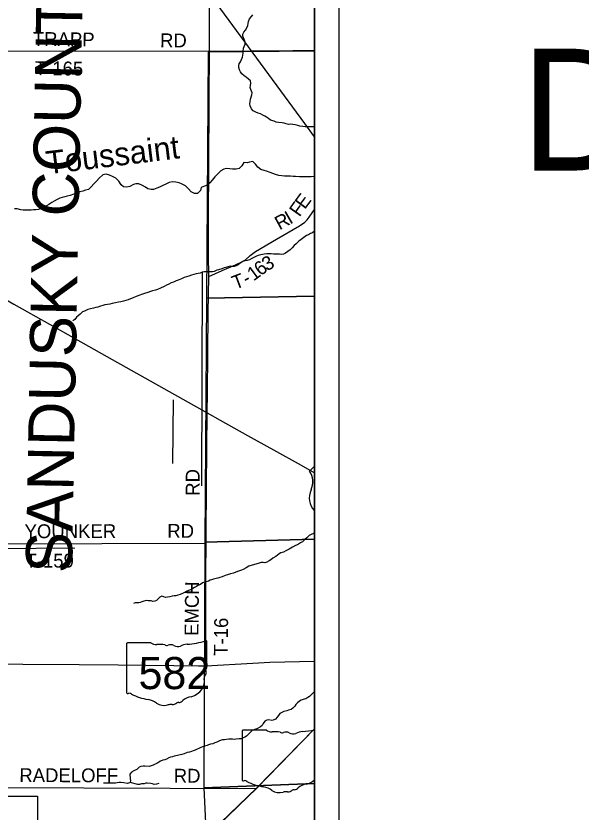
# Model space of a CAD drawing. Extents: x 0 to 34, y 0 to 22.
# Drawn here: x 7.676 to 9.993, y 16.867 to 20.135 of the extents above; entities that cross this region are included whole.
import ezdxf

# ---------------------------------------------------------------- set-up
doc = ezdxf.new("R2010")
doc.units = 0
for name, color, linetype in [('GM_X_City_Street', 7, 'Continuous'), ('GM_X_Corporation_Text', 7, 'Continuous'), ('GM_X_County_Text', 7, 'Continuous'), ('GM_X_Major_River', 7, 'Continuous'), ('GM_X_Major_River_Text', 7, 'Continuous'), ('GM_X_Minor_River', 7, 'Continuous'), ('GM_X_Rail_Line', 7, 'Continuous'), ('GM_X_State_Location', 7, 'Continuous'), ('GM_X_State_Route', 7, 'Continuous'), ('GM_X_State_Shield', 7, 'Continuous'), ('GM_X_Township_Road', 7, 'Continuous'), ('GM_X_Township_Road_Text', 7, 'Continuous'), ('GM_X_US_Route', 7, 'Continuous'), ('GM_X_US_Shield', 7, 'Continuous'), ('SH_Cut_Line', 7, 'Continuous'), ('SH_Data', 7, 'Continuous'), ('SH_Text', 7, 'Continuous')]:
    doc.layers.add(name, color=color, linetype=linetype)

msp = doc.modelspace()

# ---------------------------------------------------------------- linework, layer by layer
at = {"layer": 'GM_X_City_Street'}
for points in [[(8.9, 18.9838), (8.9, 19.99), (8.465, 19.986), (8.4572, 18.9756)], [(8.9, 17.9873), (8.9, 18.9838), (8.4572, 18.9756), (8.451, 17.9744)], [(8.9, 16.9842), (8.9, 17.9873), (8.451, 17.9744), (8.447, 16.9667)], [(8.9, 16.0164), (8.9, 16.9842), (8.447, 16.9667), (8.4914, 16.018), (8.4978, 16.0183)]]:
    msp.add_lwpolyline(points, close=True, dxfattribs=at)
at = {"layer": 'GM_X_Corporation_Text'}
for p, q in [((8.6032, 17.1993), (8.6032, 16.9992)), ((8.7029, 17.2028), (8.6063, 17.2028)), ((8.9, 16.9992), (8.9, 17.2043))]:
    msp.add_line(p, q, dxfattribs=at)
for centre, major_axis, start_param, end_param in [((8.6069, 17.1997), (0.00382, 0), 1.727492, 3.291633), ((8.7259, 17.226), (0.037, 0), 4.042888, 4.731792), ((8.7382, 17.0904), (0.133, 0), 1.404758, 1.657859), ((8.7684, 17.2008), (0.0107, 0), 3.836095, 5.185415), ((8.7841, 17.1776), (0.0222, 0), 0.950623, 2.079405), ((8.8127, 17.2094), (0.0267, 0), 4.08156, 5.145723), ((8.8599, 17.1416), (0.0703, 0), 1.699012, 2.107814), ((8.8153, 17.4756), (0.3495, 0), 4.814394, 4.957024), ((8.607, 16.9988), (0.00385, 0), 2.993084, 4.5083), ((8.6076, 17.0192), (0.0294, 0), 4.665946, 4.897461), ((8.6136, 16.9876), (0.0106, 0), 0.519207, 1.627899), ((8.7474, 17.1674), (0.2524, 0), 4.195997, 4.488961), ((8.8349, 17.0459), (0.0874, 0), 5.101753, 5.55198), ((8.6721, 16.9093), (0.079, 0), 0.823519, 1.323587), ((8.8111, 16.9798), (0.0282, 0), 4.937069, 5.64225), ((8.8718, 16.943), (0.0479, 0), 1.647645, 2.488434), ((8.7576, 16.9867), (0.0501, 0), 4.026481, 4.996735), ((8.7865, 16.9175), (0.0412, 0), 1.495662, 1.94098), ((8.7902, 16.9717), (0.0267, 0), 4.691044, 5.507374), ((8.8143, 16.9523), (0.00752, 0), 1.147584, 2.315152)]:
    msp.add_ellipse(centre, major_axis=major_axis, ratio=0.8, start_param=start_param, end_param=end_param, dxfattribs=at)
at = {"layer": 'GM_X_Major_River'}
for points in [[(8.9, 19.4752), (8.8872, 19.4736), (8.8747, 19.4741), (8.8644, 19.4738), (8.8504, 19.4735), (8.8394, 19.4744), (8.8227, 19.4757), (8.8125, 19.4761), (8.8019, 19.477), (8.7924, 19.477), (8.7769, 19.4775), (8.767, 19.4776), (8.7542, 19.4792), (8.7402, 19.4843), (8.7292, 19.4881), (8.7183, 19.4924), (8.7039, 19.4971), (8.6941, 19.5002), (8.6797, 19.5041), (8.6681, 19.5137), (8.6583, 19.5266), (8.6478, 19.537), (8.6345, 19.5348), (8.6243, 19.5322), (8.611, 19.5327), (8.6022, 19.5199), (8.5911, 19.5086), (8.5785, 19.5053), (8.5641, 19.5054), (8.5531, 19.507), (8.5399, 19.5078), (8.5285, 19.5056), (8.5163, 19.4982), (8.5037, 19.4865), (8.4922, 19.4741), (8.4803, 19.4609), (8.4715, 19.4492), (8.4608, 19.4402), (8.4494, 19.4357), (8.4353, 19.4305), (8.4325, 19.4176)], [(8.4325, 19.4176), (8.4207, 19.4059), (8.4085, 19.406), (8.3953, 19.4122), (8.3841, 19.4252), (8.3713, 19.4374), (8.3573, 19.4444), (8.3453, 19.4494), (8.3313, 19.4529), (8.3165, 19.4534), (8.3047, 19.4509), (8.288, 19.443), (8.2785, 19.4385), (8.2644, 19.4318), (8.2545, 19.4277), (8.2408, 19.4225), (8.2309, 19.4222), (8.2169, 19.4254), (8.2071, 19.4311), (8.1947, 19.4392), (8.1796, 19.4458), (8.1682, 19.4459), (8.1583, 19.4425), (8.1438, 19.4347), (8.1309, 19.4313), (8.1177, 19.4337), (8.1079, 19.4414), (8.0974, 19.4563), (8.0858, 19.4693), (8.0722, 19.4754), (8.0594, 19.4805), (8.0461, 19.4844), (8.0325, 19.4826), (8.0172, 19.4683), (8.0068, 19.457), (7.9731, 19.4217)], [(7.9731, 19.4217), (7.9618, 19.419), (7.9503, 19.4153), (7.9382, 19.412), (7.9272, 19.4075), (7.9131, 19.4023), (7.8979, 19.3979), (7.8865, 19.3949), (7.8766, 19.3924), (7.866, 19.3894), (7.8564, 19.3861), (7.8446, 19.3808), (7.8332, 19.3741), (7.8237, 19.3685), (7.8111, 19.361), (7.8016, 19.3554), (7.7905, 19.3498), (7.778, 19.3438), (7.7685, 19.3401), (7.7578, 19.3383), (7.7483, 19.338), (7.7385, 19.3373), (7.7282, 19.3374), (7.7188, 19.337), (7.7059, 19.3371), (7.6957, 19.3387), (7.6813, 19.3427), (7.6707, 19.3431)]]:
    msp.add_lwpolyline(points, dxfattribs=at)
at = {"layer": 'GM_X_Minor_River'}
for p, q in [((8.4397, 19.0823), (8.437, 18.2059)), ((8.3212, 18.5591), (8.3176, 18.2977)), ((7.9171, 17.9505), (7.5206, 17.947))]:
    msp.add_line(p, q, dxfattribs=at)
for points in [[(8.9, 19.6791), (8.8972, 19.68), (8.8888, 19.6796), (8.8809, 19.6792), (8.8721, 19.6791), (8.8623, 19.6794), (8.852, 19.6801), (8.8402, 19.6827), (8.8326, 19.6842), (8.8209, 19.688), (8.8114, 19.689), (8.8034, 19.6898), (8.7943, 19.6893), (8.7844, 19.6919), (8.7761, 19.6942), (8.7681, 19.6953), (8.7529, 19.6971), (8.7427, 19.6986), (8.7347, 19.7027), (8.7206, 19.7072), (8.7115, 19.7132), (8.7039, 19.7196), (8.6963, 19.7237), (8.6887, 19.7275), (8.6784, 19.732), (8.67, 19.7354), (8.6602, 19.7391), (8.6484, 19.7447), (8.6419, 19.7534), (8.6365, 19.7652), (8.6354, 19.7739), (8.6365, 19.7826), (8.6383, 19.7933), (8.6428, 19.81), (8.6443, 19.8191), (8.6397, 19.8332), (8.6366, 19.8407), (8.6381, 19.8491), (8.6396, 19.859), (8.6384, 19.8685), (8.6304, 19.8756), (8.6202, 19.8828), (8.6114, 19.888), (8.6026, 19.8975), (8.5965, 19.9054), (8.5935, 19.9138), (8.59, 19.9229), (8.5896, 19.9305), (8.5919, 19.9384), (8.5964, 19.9464), (8.6005, 19.9556), (8.6047, 19.9655), (8.6065, 19.9731), (8.608, 19.9814), (8.608, 19.989), (8.6095, 20.0015), (8.6125, 20.0095), (8.6166, 20.0187), (8.6158, 20.0263), (8.6127, 20.0353), (8.6066, 20.0513), (8.607, 20.0592), (8.6107, 20.068), (8.6168, 20.0756), (8.6232, 20.0863), (8.6273, 20.0946), (8.6288, 20.1034), (8.6295, 20.1121), (8.6344, 20.1228), (8.6416, 20.1315), (8.6476, 20.1395)], [(8.9, 19.2509), (8.892, 19.2449), (8.8844, 19.2411), (8.8761, 19.2357), (8.867, 19.233), (8.8572, 19.2258), (8.8458, 19.2174), (8.8367, 19.2101), (8.8254, 19.1998), (8.8174, 19.1929), (8.8091, 19.183), (8.8004, 19.175), (8.7913, 19.1681), (8.7815, 19.1608), (8.7732, 19.157), (8.7648, 19.1551), (8.7569, 19.1562), (8.7477, 19.1569), (8.7402, 19.1572), (8.7326, 19.1572), (8.7231, 19.1575), (8.7132, 19.1586), (8.7045, 19.1585), (8.6935, 19.1562), (8.6806, 19.1542), (8.67, 19.1511), (8.6624, 19.1481), (8.6544, 19.1442), (8.6438, 19.1396), (8.634, 19.1339), (8.6241, 19.1308), (8.6147, 19.1288), (8.6059, 19.1265), (8.5961, 19.1196), (8.5878, 19.1131), (8.5791, 19.1082), (8.5715, 19.1058), (8.5635, 19.1062), (8.5559, 19.1069), (8.5453, 19.1049), (8.537, 19.1026), (8.5294, 19.1003), (8.5207, 19.0972), (8.5074, 19.093), (8.4998, 19.091), (8.4892, 19.086), (8.4816, 19.0845), (8.4725, 19.0848), (8.4649, 19.084), (8.4558, 19.0836), (8.4479, 19.0847), (8.4399, 19.0824), (8.4316, 19.0793), (8.4149, 19.0754)], [(8.4149, 19.0754), (8.405, 19.0727), (8.3963, 19.0707), (8.3857, 19.0669), (8.3755, 19.0638), (8.3664, 19.0607), (8.355, 19.0557), (8.3417, 19.05), (8.3334, 19.0469), (8.3217, 19.0423), (8.3133, 19.0388), (8.3031, 19.0338), (8.2936, 19.0292), (8.2845, 19.0242), (8.2683, 19.0177), (8.2569, 19.0123), (8.2478, 19.0096), (8.2364, 19.0058), (8.2273, 19.003), (8.2163, 18.9996), (8.2035, 18.9957), (8.1947, 18.9919), (8.1803, 18.9869), (8.1694, 18.9826), (8.1572, 18.978), (8.1455, 18.9734), (8.1368, 18.9699), (8.1273, 18.9668), (8.1174, 18.9637), (8.1057, 18.9614), (8.0966, 18.9595), (8.0841, 18.9571), (8.0712, 18.954), (8.0606, 18.9517), (8.0515, 18.9497), (8.0412, 18.9482), (8.0329, 18.9455), (8.023, 18.9427), (8.012, 18.9397), (8.0033, 18.9381), (7.9935, 18.9354), (7.9821, 18.933), (7.9711, 18.9299), (7.9571, 18.9234), (7.9495, 18.92), (7.9397, 18.9108), (7.9317, 18.9043), (7.9242, 18.8978), (7.9174, 18.8887), (7.9094, 18.8829)], [(8.9, 18.0106), (8.8967, 18.0105), (8.8861, 18.0066), (8.8781, 18.002), (8.869, 17.9921), (8.8603, 17.9852), (8.8505, 17.9764), (8.8425, 17.9715), (8.8301, 17.9638), (8.8229, 17.9615), (8.81, 17.9546), (8.7964, 17.9462), (8.7835, 17.9397), (8.7729, 17.9335), (8.763, 17.9308), (8.7554, 17.9262), (8.7414, 17.9159), (8.729, 17.9086), (8.7214, 17.9021), (8.715, 17.8975), (8.7055, 17.8933), (8.6971, 17.8902), (8.6896, 17.8906), (8.6823, 17.8909), (8.6736, 17.889), (8.66, 17.8847), (8.6444, 17.8808), (8.6312, 17.8758), (8.6202, 17.8689), (8.6081, 17.8628), (8.6005, 17.8594), (8.5929, 17.857), (8.5842, 17.854), (8.5687, 17.8474), (8.5565, 17.8451), (8.5437, 17.8405), (8.5334, 17.8377), (8.5224, 17.8324), (8.5126, 17.8297), (8.5035, 17.8273), (8.4967, 17.8254), (8.4864, 17.8231), (8.4785, 17.8207), (8.472, 17.8181), (8.4656, 17.815), (8.4557, 17.8123), (8.4489, 17.8103), (8.4417, 17.8084), (8.4334, 17.8012), (8.4224, 17.7969), (8.416, 17.7931), (8.408, 17.7885), (8.4008, 17.785), (8.3913, 17.7789), (8.3834, 17.7762), (8.3743, 17.7716), (8.3652, 17.7666), (8.3588, 17.7639), (8.3501, 17.7597), (8.3406, 17.7574), (8.3322, 17.7547), (8.3243, 17.7539), (8.3171, 17.7531), (8.3068, 17.7508), (8.2974, 17.7496), (8.2894, 17.7476), (8.2826, 17.751), (8.2738, 17.7529), (8.2655, 17.7494), (8.2591, 17.7422), (8.2523, 17.7357), (8.2451, 17.7322), (8.2375, 17.7318), (8.2303, 17.7333), (8.2181, 17.734)], [(8.2181, 17.734), (8.2101, 17.7351), (8.2003, 17.7331), (8.1923, 17.73), (8.1859, 17.7277), (8.1794, 17.7258), (8.1726, 17.7258), (8.1646, 17.7253), (8.1582, 17.723)], [(8.9, 17.3626), (8.8957, 17.3576), (8.8885, 17.3496), (8.8799, 17.3412), (8.8727, 17.3369), (8.8647, 17.3323), (8.8579, 17.3297), (8.8458, 17.3258), (8.8393, 17.322), (8.8302, 17.3151), (8.8234, 17.309), (8.82, 17.3017), (8.811, 17.2933), (8.8045, 17.288), (8.7939, 17.2849), (8.7867, 17.2826), (8.7742, 17.2799), (8.7576, 17.2714), (8.753, 17.2631), (8.7474, 17.2566), (8.7406, 17.2486), (8.7315, 17.2443), (8.725, 17.2432), (8.7133, 17.2458), (8.7053, 17.2438), (8.697, 17.24), (8.6905, 17.2305), (8.6853, 17.2228), (8.6785, 17.2164), (8.6637, 17.2083), (8.6538, 17.2056), (8.6447, 17.2014), (8.6364, 17.1941), (8.6304, 17.1865), (8.6209, 17.1781), (8.6145, 17.1743), (8.608, 17.1719), (8.5997, 17.1681), (8.5921, 17.1669), (8.5792, 17.1657), (8.5713, 17.1653), (8.5644, 17.1664), (8.5572, 17.1667), (8.5493, 17.1663), (8.539, 17.1648), (8.5307, 17.1639), (8.5238, 17.1632), (8.517, 17.1616), (8.5083, 17.1578), (8.5, 17.1539), (8.4916, 17.1508), (8.4829, 17.147), (8.4738, 17.1454), (8.4662, 17.1427), (8.4598, 17.1408), (8.4499, 17.137), (8.4412, 17.1343), (8.4344, 17.1319), (8.4257, 17.1281), (8.4193, 17.1254), (8.4105, 17.1208), (8.4033, 17.1181), (8.3958, 17.1158), (8.3874, 17.1127), (8.3783, 17.1108), (8.3662, 17.1054), (8.356, 17.1031), (8.3495, 17.1015), (8.3389, 17.0988), (8.3245, 17.0961), (8.3181, 17.0937), (8.3097, 17.0918), (8.3029, 17.0891), (8.2934, 17.0841), (8.287, 17.0818), (8.2787, 17.0795)], [(8.2787, 17.0795), (8.2692, 17.0756), (8.2616, 17.0718), (8.254, 17.0665), (8.2465, 17.0634), (8.2385, 17.0599), (8.2302, 17.0561), (8.223, 17.0545), (8.2047, 17.056), (8.1983, 17.0555), (8.1877, 17.054), (8.1809, 17.0509), (8.1725, 17.0421), (8.1657, 17.0387), (8.1593, 17.0364), (8.1498, 17.0302), (8.143, 17.023), (8.143, 17.0165), (8.1442, 17.0097), (8.145, 17.0033), (8.1454, 16.996), (8.1451, 16.9888)], [(8.1452, 16.9888), (8.1329, 16.9842), (8.1185, 16.9864), (8.1063, 16.9882), (8.0991, 16.9878), (8.0912, 16.9863), (8.0847, 16.9855), (8.0752, 16.985), (8.0673, 16.9858), (8.0589, 16.9857), (8.0521, 16.9853), (8.035, 16.9852)], [(8.2616, 16.9845), (8.2525, 16.9818), (8.243, 16.9806), (8.2358, 16.9825), (8.2286, 16.9836), (8.2149, 16.9858), (8.2081, 16.9857), (8.2016, 16.9834), (8.1914, 16.9822), (8.183, 16.9807), (8.1762, 16.9803), (8.1451, 16.9888)]]:
    msp.add_lwpolyline(points, dxfattribs=at)
at = {"layer": 'GM_X_Rail_Line'}
for points in [[(8.9, 19.6389), (8.8604, 19.6932), (8.4181, 20.2972), (7.9759, 20.9)], [(7.4742, 16.0534), (7.8661, 16.2441), (7.8862, 16.2455), (8.0808, 16.409), (8.1603, 16.4709), (8.5168, 16.8244), (8.6624, 16.9647), (8.9, 17.2081)]]:
    msp.add_lwpolyline(points, dxfattribs=at)
at = {"layer": 'GM_X_State_Route'}
for points in [[(7.5031, 17.4755), (7.7045, 17.4738), (7.9348, 17.4725), (8.0957, 17.4713), (8.3231, 17.4688), (8.4251, 17.4674), (8.4546, 17.4677), (8.6481, 17.4781), (8.7174, 17.4818), (8.9, 17.4864)], [(7.4722, 15.887), (7.5101, 15.9321), (7.7055, 16.1117), (7.8205, 16.2154), (8.0065, 16.3511), (8.0705, 16.3981), (8.1716, 16.4806), (8.2905, 16.5979), (8.4388, 16.7459), (8.5901, 16.8939), (8.6621, 16.9631), (8.9, 17.2081)]]:
    msp.add_lwpolyline(points, dxfattribs=at)
at = {"layer": 'GM_X_State_Shield'}
for p, q in [((8.1298, 17.5576), (8.1298, 17.3575)), ((8.2296, 17.5611), (8.1331, 17.5611)), ((8.4594, 17.4614), (8.4594, 17.566)), ((8.4594, 17.4614), (8.4594, 17.4614))]:
    msp.add_line(p, q, dxfattribs=at)
for centre, major_axis, start_param, end_param in [((8.1336, 17.5581), (0.00382, 0), 1.712693, 3.28349), ((8.2526, 17.5843), (0.037, 0), 4.042523, 4.731795), ((8.2649, 17.4487), (0.133, 0), 1.404758, 1.657858), ((8.295, 17.5591), (0.0107, 0), 3.836095, 5.185415), ((8.3107, 17.536), (0.0222, 0), 0.950623, 2.079405), ((8.3394, 17.5677), (0.0267, 0), 4.081561, 5.145723), ((8.3866, 17.5), (0.0703, 0), 1.699011, 2.107814), ((8.342, 17.8339), (0.3495, 0), 4.814394, 5.042369), ((8.4558, 17.5665), (0.00367, 0), 6.141152, 7.989035), ((8.4586, 17.4537), (0.00568, 0), 1.883978, 3.671073), ((8.4224, 17.4404), (0.0341, 0), 5.934695, 6.695948), ((8.4555, 17.461), (0.00393, 0), 5.05454, 6.418171), ((8.4726, 17.4175), (0.0248, 0), 2.387724, 3.262537), ((8.3616, 17.4042), (0.0874, 0), 5.101752, 6.440018), ((8.1336, 17.3571), (0.00385, 0), 3.00124, 4.508301), ((8.1342, 17.3776), (0.0294, 0), 4.665946, 4.897461), ((8.1402, 17.346), (0.0106, 0), 0.519207, 1.627899), ((8.2741, 17.5258), (0.2524, 0), 4.195997, 4.488961), ((8.1988, 17.2676), (0.079, 0), 0.823519, 1.323587), ((8.3378, 17.3381), (0.0282, 0), 4.937069, 5.64225), ((8.3985, 17.3013), (0.0479, 0), 1.647645, 2.488434), ((8.2842, 17.345), (0.0501, 0), 4.026481, 4.996735), ((8.3132, 17.2758), (0.0412, 0), 1.495662, 1.94098), ((8.3168, 17.33), (0.0267, 0), 4.691044, 5.507374), ((8.341, 17.3106), (0.00752, 0), 1.147584, 2.315152)]:
    msp.add_ellipse(centre, major_axis=major_axis, ratio=0.8, start_param=start_param, end_param=end_param, dxfattribs=at)
at = {"layer": 'GM_X_Township_Road'}
for p, q in [((8.4697, 19.9905), (8.4711, 20.9)), ((7.5482, 19.9914), (8.4697, 19.9905)), ((7.5111, 17.9676), (8.4557, 17.9711)), ((7.4942, 16.968), (8.6621, 16.9631))]:
    msp.add_line(p, q, dxfattribs=at)
for points in [[(8.4672, 19.0651), (8.4657, 19.154), (8.4664, 19.312), (8.4674, 19.5121), (8.4681, 19.7934), (8.4697, 19.9905)], [(8.4697, 19.9905), (8.811, 19.9922), (8.9, 19.9928)], [(8.4672, 19.0651), (8.5212, 19.0896), (8.5763, 19.1132), (8.6057, 19.1262), (8.6174, 19.1334), (8.6361, 19.151), (8.6469, 19.1599), (8.6586, 19.1678), (8.744, 19.2177), (8.8382, 19.2728), (8.8608, 19.2878), (8.8705, 19.2978), (8.879, 19.3087), (8.9, 19.3403)], [(8.4602, 18.5051), (8.4621, 18.5884), (8.4635, 18.7479), (8.465, 18.9166), (8.4672, 19.0651)], [(8.4546, 17.4677), (8.4546, 17.6558), (8.4551, 17.8469), (8.4557, 17.9711), (8.4562, 18.0177), (8.4577, 18.1949), (8.4587, 18.3609), (8.4602, 18.5051)]]:
    msp.add_lwpolyline(points, dxfattribs=at)
at = {"layer": 'GM_X_US_Route'}
for points in [[(8.9, 14.5091), (8.9, 20.9)], [(7.6072, 18.9851), (7.6673, 18.9512), (7.8132, 18.8691), (8.0488, 18.7365), (8.4602, 18.5051), (8.5129, 18.4758), (8.6254, 18.4131), (8.7327, 18.353), (8.8455, 18.2902), (8.9, 18.2599)]]:
    msp.add_lwpolyline(points, dxfattribs=at)
at = {"layer": 'GM_X_US_Shield'}
msp.add_lwpolyline([(8.9, 18.1035), (8.9, 18.2866), (8.8797, 18.2663)], dxfattribs=at)
for centre, start, end in [((8.8167, 18.2222), 334.5471, 35.0009), ((8.9558, 18.1564), 154.8319, 223.5155)]:
    msp.add_arc(centre, 0.0769, start, end, dxfattribs=at)
at = {"layer": 'SH_Cut_Line'}
msp.add_lwpolyline([(8.9, 14.1), (8.9, 20.9)], dxfattribs=at)
at = {"layer": 'SH_Data'}
for p, q in [((9, 21), (9, 14)), ((8.9, 20.9), (8.9, 14.1))]:
    msp.add_line(p, q, dxfattribs=at)
at = {"layer": 'SH_Text'}
msp.add_lwpolyline([(5.7647, 16.9319), (7.7647, 16.9319), (7.7647, 16.1819), (5.7647, 16.1819)], close=True, dxfattribs=at)

# ---------------------------------------------------------------- texts
at = {"layer": 'GM_X_County_Text'}
msp.add_text('SANDUSKY COUNTY', height=0.189394, rotation=88.9341, dxfattribs=at).set_placement((7.9054, 17.8465))
at = {"layer": 'GM_X_Major_River_Text'}
msp.add_text('Toussaint', height=0.09476, rotation=6.9412, dxfattribs=at).set_placement((7.8052, 19.4842))
at = {"layer": 'GM_X_State_Location'}
for s, p in [('582', (8.2241, 17.4305)), ('105', (8.6974, 17.0722))]:
    msp.add_text(s, height=0.000189, rotation=0, dxfattribs=at).set_placement(p)
for s, p in [('s', (8.2909, 17.4443)), ('r', (8.2909, 17.4443)), ('s', (8.7643, 17.0859)), ('r', (8.7642, 17.0859))]:
    msp.add_text(s, height=0.000189, dxfattribs=at).set_placement(p)
at = {"layer": 'GM_X_State_Shield'}
msp.add_text('582', height=0.13184, dxfattribs=at).set_placement((8.1788, 17.3716))
at = {"layer": 'GM_X_Township_Road_Text'}
for s, height, rotation, p in [('TRAPP', 0.05682, 359.3359, (7.7451, 20.0119)), ('RD', 0.05682, 359.5064, (8.2667, 20.006)), ('T-165', 0.05682, 359.4386, (7.7531, 19.8916)), ('E', 0.0568, 53.6418, (8.8606, 19.3378)), ('F', 0.0568, 54.8301, (8.8387, 19.3068)), ('R', 0.0568, 28.6653, (8.757, 19.2542)), ('I', 0.0568, 30.2823, (8.7995, 19.2775)), ('3', 0.0568, 30.8687, (8.7056, 19.0853)), ('6', 0.0568, 36.643, (8.6788, 19.0652)), ('1', 0.0568, 36.3276, (8.6503, 19.0443)), ('T', 0.0568, 20.6967, (8.575, 19.0105)), ('-', 0.0568, 27.3895, (8.6214, 19.0285)), ('RD', 0.05682, 90, (8.4292, 18.1652)), ('YOUNKER', 0.05682, 0.1412, (7.7115, 17.9909)), ('RD', 0.05682, 0, (8.2966, 17.9926)), ('T-159', 0.05682, 0.2818, (7.7154, 17.8699)), ('EMCH', 0.05682, 89.2867, (8.4242, 17.5897)), ('T-16', 0.05682, 89.2924, (8.5443, 17.5082)), ('RADELOFF', 0.05682, 359.8666, (7.6899, 16.9901)), ('RD', 0.05682, 0, (8.3232, 16.9876))]:
    msp.add_text(s, height=height, rotation=rotation, dxfattribs=at).set_placement(p)
at = {"layer": 'SH_Text'}
msp.add_text('DEPARTMENT OF TRANSPORTATION', height=0.5, dxfattribs=at).set_placement((9.7466, 19.5))

doc.saveas('drawing.dxf')
